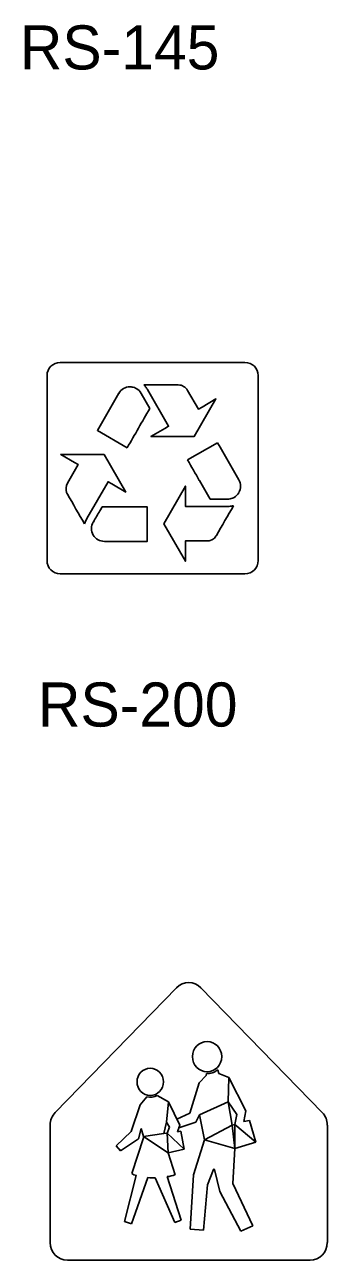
# Model space of a CAD drawing. Extents: x 42133 to 45533, y 41351 to 47951.
# Drawn here: x 43339.4 to 43390.9, y 42003.1 to 42213.3 of the extents above; entities that cross this region are included whole.
import ezdxf

# ---------------------------------------------------------------- set-up
doc = ezdxf.new("R2010")
doc.units = 0
doc.layers.add('P_TRAF_SIGN_SignDetails', color=7, linetype='Continuous')

msp = doc.modelspace()

# ---------------------------------------------------------------- linework, layer by layer
at = {"layer": 'P_TRAF_SIGN_SignDetails'}
for p, q in [((43376.91, 42155.87), (43345.43, 42155.87)), ((43343.18, 42153.62), (43343.18, 42122.14)), ((43379.16, 42122.14), (43379.16, 42153.62)), ((43345.43, 42119.88), (43376.91, 42119.88)), ((43365.24, 42049.48), (43344.58, 42028.24)), ((43369.41, 42049.48), (43390.07, 42028.24)), ((43372.19, 42035.5), (43372.3, 42035.42)), ((43372.3, 42035.42), (43372.47, 42034.89)), ((43367.52, 42028.11), (43369.1, 42033.31)), ((43369.1, 42033.31), (43370.32, 42034.52)), ((43370.34, 42034.89), (43370.32, 42034.52)), ((43370.32, 42034.52), (43370.34, 42034.89)), ((43372.47, 42034.89), (43374.15, 42034.22)), ((43374.02, 42030.08), (43374.15, 42034.22)), ((43374.15, 42034.22), (43377.03, 42028.55)), ((43361.96, 42031.14), (43363.86, 42030.06)), ((43361.96, 42031.14), (43363.86, 42030.06)), ((43357.52, 42025), (43359.03, 42029.53)), ((43357.52, 42025), (43359.03, 42029.53)), ((43359.03, 42029.53), (43360.21, 42030.89)), ((43359.03, 42029.53), (43360.21, 42030.89)), ((43363.53, 42026.61), (43363.86, 42030.06)), ((43365.79, 42026.1), (43363.86, 42030.06)), ((43365.79, 42026.1), (43363.86, 42030.06)), ((43363.86, 42030.06), (43365.79, 42026.1)), ((43363.86, 42030.06), (43365.79, 42026.1)), ((43363.95, 42029.87), (43363.95, 42029.87)), ((43364.16, 42029.46), (43364.16, 42029.46)), ((43364.36, 42029.04), (43364.36, 42029.04)), ((43374.02, 42030.08), (43369.14, 42027.87)), ((43369.14, 42027.87), (43374.02, 42030.08)), ((43375.54, 42027.88), (43374.02, 42030.08)), ((43374.73, 42026.1), (43374.02, 42030.08)), ((43374.02, 42030.08), (43375.54, 42027.88)), ((43375.54, 42027.88), (43374.02, 42030.08)), ((43374.02, 42030.08), (43374.73, 42026.1)), ((43375.54, 42027.88), (43374.02, 42030.08)), ((43374.02, 42030.08), (43374.73, 42026.1)), ((43364.56, 42028.63), (43364.56, 42028.63)), ((43364.76, 42028.21), (43364.76, 42028.21)), ((43364.97, 42027.8), (43364.97, 42027.8)), ((43365.16, 42027.39), (43365.16, 42027.39)), ((43365.3, 42027.11), (43367.52, 42028.11)), ((43369.14, 42027.87), (43368.52, 42026.58)), ((43370.03, 42023.59), (43369.14, 42027.87)), ((43375.18, 42026.2), (43375.54, 42027.88)), ((43375.18, 42026.2), (43375.54, 42027.88)), ((43377.03, 42028.55), (43376.72, 42026.69)), ((43376.72, 42026.69), (43377.7, 42026.89)), ((43377.7, 42026.89), (43378.77, 42023.17)), ((43343.71, 42026.1), (43343.71, 42006.13)), ((43354.95, 42022.56), (43357.52, 42025)), ((43354.95, 42022.56), (43357.52, 42025)), ((43359.24, 42025.5), (43358.77, 42023.76)), ((43359.24, 42025.5), (43358.77, 42023.76)), ((43359.61, 42024.13), (43359.24, 42025.5)), ((43359.61, 42024.13), (43359.24, 42025.5)), ((43363.53, 42026.61), (43363.07, 42024.69)), ((43364.03, 42025.77), (43363.53, 42026.61)), ((43363.63, 42024.73), (43364.03, 42025.77)), ((43365.79, 42026.1), (43365.4, 42024.95)), ((43365.4, 42024.95), (43365.79, 42026.1)), ((43365.79, 42026.1), (43365.4, 42024.95)), ((43365.79, 42026.1), (43365.4, 42024.95)), ((43365.4, 42024.95), (43366, 42025.06)), ((43365.4, 42024.95), (43366, 42025.06)), ((43368.52, 42026.58), (43365.62, 42025.61)), ((43365.66, 42025.73), (43365.66, 42025.73)), ((43365.66, 42025.73), (43365.66, 42025.73)), ((43366, 42025.06), (43366.57, 42022.01)), ((43366, 42025.06), (43366.57, 42022.01)), ((43374.73, 42026.1), (43370.03, 42023.59)), ((43375.18, 42026.2), (43374.73, 42026.1)), ((43374.73, 42026.1), (43375.15, 42022.11)), ((43375.15, 42022.11), (43375.18, 42026.2)), ((43375.15, 42022.11), (43375.18, 42026.2)), ((43378.77, 42023.17), (43375.18, 42026.2)), ((43375.18, 42026.2), (43378.77, 42023.17)), ((43390.94, 42026.1), (43390.94, 42006.13)), ((43358.77, 42023.76), (43355.7, 42021.73)), ((43358.77, 42023.76), (43355.7, 42021.73)), ((43357.6, 42017.86), (43359.59, 42023.91)), ((43357.6, 42017.86), (43359.59, 42023.91)), ((43359.59, 42023.91), (43359.61, 42024.13)), ((43359.59, 42023.91), (43359.61, 42024.13)), ((43363.07, 42024.69), (43359.61, 42024.13)), ((43363.07, 42024.69), (43359.61, 42024.13)), ((43359.61, 42024.13), (43363.84, 42021.36)), ((43359.61, 42024.13), (43363.84, 42021.36)), ((43363.63, 42024.73), (43363.07, 42024.69)), ((43366.57, 42022.01), (43363.63, 42024.73)), ((43363.84, 42021.36), (43363.63, 42024.73)), ((43363.63, 42024.73), (43366.57, 42022.01)), ((43368.14, 42017.66), (43370.03, 42023.59)), ((43375.15, 42022.11), (43370.03, 42023.59)), ((43370.03, 42023.59), (43375.15, 42022.11)), ((43370.03, 42023.59), (43375.15, 42022.11)), ((43375.15, 42022.11), (43370.03, 42023.59)), ((43375.15, 42022.11), (43370.03, 42023.59)), ((43370.03, 42023.59), (43375.15, 42022.11)), ((43370.03, 42023.59), (43375.15, 42022.11)), ((43375.15, 42022.11), (43370.03, 42023.59)), ((43375.15, 42022.11), (43370.03, 42023.59)), ((43370.03, 42023.59), (43375.15, 42022.11)), ((43378.77, 42023.17), (43375.15, 42022.11)), ((43355.7, 42021.73), (43354.95, 42022.56)), ((43355.7, 42021.73), (43354.95, 42022.56)), ((43355.63, 42021.82), (43355.83, 42021.82)), ((43366.57, 42022.01), (43363.84, 42021.36)), ((43366.57, 42022.01), (43363.84, 42021.36)), ((43363.84, 42021.36), (43365.01, 42017.66)), ((43363.84, 42021.36), (43365.01, 42017.66)), ((43375.15, 42022.11), (43374.85, 42016.14)), ((43371.52, 42018.53), (43370.52, 42015.93)), ((43372.6, 42014.77), (43371.72, 42018.53)), ((43356.38, 42009.69), (43358.39, 42017.54)), ((43356.38, 42009.69), (43358.39, 42017.54)), ((43360.37, 42017.18), (43357.55, 42009.32)), ((43360.37, 42017.18), (43357.55, 42009.32)), ((43364.97, 42009.51), (43361.61, 42017.12)), ((43364.97, 42009.51), (43361.61, 42017.12)), ((43363.65, 42017.33), (43366.04, 42009.93)), ((43363.65, 42017.33), (43366.04, 42009.93)), ((43367.56, 42008.38), (43368.14, 42017.66)), ((43370.52, 42015.93), (43369.83, 42008.21)), ((43376.21, 42008.02), (43372.6, 42014.77)), ((43374.85, 42016.14), (43378.22, 42008.97)), ((43357.55, 42009.32), (43356.38, 42009.69)), ((43357.55, 42009.32), (43356.38, 42009.69)), ((43366.04, 42009.93), (43364.97, 42009.51)), ((43366.04, 42009.93), (43364.97, 42009.51)), ((43369.83, 42008.21), (43367.56, 42008.38)), ((43378.22, 42008.97), (43376.21, 42008.02)), ((43346.66, 42003.09), (43387.99, 42003.09))]:
    msp.add_line(p, q, dxfattribs=at)
for points in [[(43365.54, 42152.04), (43359.67, 42152.04)], [(43365.54, 42152.04), (43359.67, 42152.04)], [(43365.54, 42152.04), (43359.67, 42152.04)], [(43360.28, 42151.24), (43363.89, 42145), (43363.26, 42144.63), (43360.89, 42143.27), (43368.27, 42143.27), (43371.96, 42149.65), (43369.59, 42148.28), (43368.96, 42147.92), (43367.13, 42151.11)], [(43360.28, 42151.24), (43363.89, 42145), (43363.26, 42144.63), (43360.89, 42143.27), (43368.27, 42143.27), (43371.96, 42149.65), (43369.59, 42148.28), (43368.96, 42147.92), (43367.13, 42151.11)], [(43360.28, 42151.24), (43363.89, 42145), (43363.26, 42144.63), (43360.89, 42143.27), (43368.27, 42143.27), (43371.96, 42149.65), (43369.59, 42148.28), (43368.96, 42147.92), (43367.13, 42151.11)], [(43355.41, 42150.61), (43351.76, 42144.29), (43356.85, 42141.36)], [(43355.41, 42150.61), (43351.76, 42144.29), (43356.85, 42141.36)], [(43355.41, 42150.61), (43351.76, 42144.29), (43356.85, 42141.36)], [(43360.69, 42148.02), (43359.2, 42150.6)], [(43360.69, 42148.02), (43359.2, 42150.6)], [(43360.69, 42148.02), (43359.2, 42150.6)], [(43372.21, 42142.21), (43367.13, 42139.28)], [(43372.21, 42142.21), (43367.13, 42139.28)], [(43372.21, 42142.21), (43367.13, 42139.28)], [(43349.97, 42129.31), (43353.59, 42135.56), (43354.21, 42135.2), (43356.58, 42133.82), (43352.89, 42140.21), (43345.51, 42140.22), (43347.88, 42138.86), (43348.51, 42138.49), (43346.66, 42135.3)], [(43349.97, 42129.31), (43353.59, 42135.56), (43354.21, 42135.2), (43356.58, 42133.82), (43352.89, 42140.21), (43345.51, 42140.22), (43347.88, 42138.86), (43348.51, 42138.49), (43346.66, 42135.3)], [(43349.97, 42129.31), (43353.59, 42135.56), (43354.21, 42135.2), (43356.58, 42133.82), (43352.89, 42140.21), (43345.51, 42140.22), (43347.88, 42138.86), (43348.51, 42138.49), (43346.66, 42135.3)], [(43373.98, 42131.35), (43366.76, 42131.36), (43366.76, 42132.08), (43366.76, 42134.82), (43363.07, 42128.43), (43366.75, 42122.04), (43366.75, 42124.77)], [(43373.98, 42131.35), (43366.76, 42131.36), (43366.76, 42132.08), (43366.76, 42134.82), (43363.07, 42128.43), (43366.75, 42122.04), (43366.75, 42124.77)], [(43373.98, 42131.35), (43366.76, 42131.36), (43366.76, 42132.08), (43366.76, 42134.82), (43363.07, 42128.43), (43366.75, 42122.04), (43366.75, 42124.77)], [(43370.97, 42132.61), (43373.95, 42132.61)], [(43370.97, 42132.61), (43373.95, 42132.61)], [(43370.97, 42132.61), (43373.95, 42132.61)], [(43352.96, 42125.41), (43360.25, 42125.41), (43360.25, 42131.28), (43352.57, 42131.28)], [(43352.96, 42125.41), (43360.25, 42125.41), (43360.25, 42131.28), (43352.57, 42131.28)], [(43352.96, 42125.41), (43360.25, 42125.41), (43360.25, 42131.28), (43352.57, 42131.28)], [(43366.75, 42124.77), (43366.75, 42125.5), (43370.43, 42125.49)], [(43366.75, 42124.77), (43366.75, 42125.5), (43370.43, 42125.49)], [(43366.75, 42124.77), (43366.75, 42125.5), (43370.43, 42125.49)], [(43365.62, 42025.61), (43365.79, 42026.1), (43365.3, 42027.11)], [(43370.03, 42023.59), (43374.73, 42026.1), (43375.15, 42022.11)]]:
    msp.add_lwpolyline(points, dxfattribs=at)
for centre, radius, start, end in [((43345.43, 42153.62), 2.25, 90, 180), ((43376.91, 42153.62), 2.25, 360, 90), ((43357.32, 42149.53), 2.18, 90.2881, 150.4934), ((43357.32, 42149.53), 2.18, 90.2881, 150.4934), ((43357.32, 42149.53), 2.18, 90.2881, 150.4934), ((43357.26, 42149.32), 2.39, 79.4497, 88.9151), ((43357.26, 42149.32), 2.39, 79.4497, 88.9151), ((43357.26, 42149.32), 2.39, 79.4497, 88.9151), ((43357.31, 42149.56), 2.15, 59.845, 79.6127), ((43357.31, 42149.56), 2.15, 59.845, 79.6127), ((43357.31, 42149.56), 2.15, 59.845, 79.6127), ((43357.33, 42149.55), 2.15, 29.1343, 60.3192), ((43357.33, 42149.55), 2.15, 29.1343, 60.3192), ((43357.33, 42149.55), 2.15, 29.1343, 60.3192), ((43355.02, 42147.7), 6.37, 40.2231, 43.031), ((43355.02, 42147.7), 6.37, 40.2231, 43.031), ((43355.02, 42147.7), 6.37, 40.2231, 43.031), ((43356.96, 42149.31), 3.84, 32.0576, 40.4922), ((43356.96, 42149.31), 3.84, 32.0576, 40.4922), ((43356.96, 42149.31), 3.84, 32.0576, 40.4922), ((43357.55, 42149.7), 3.14, 29.4949, 31.8189), ((43357.55, 42149.7), 3.14, 29.4949, 31.8189), ((43357.55, 42149.7), 3.14, 29.4949, 31.8189), ((43365.55, 42150.24), 1.8, 59.8496, 90.2116), ((43365.55, 42150.24), 1.8, 59.8496, 90.2116), ((43365.55, 42150.24), 1.8, 59.8496, 90.2116), ((43365.49, 42150.18), 1.88, 29.8933, 59.4501), ((43365.49, 42150.18), 1.88, 29.8933, 59.4501), ((43365.49, 42150.18), 1.88, 29.8933, 59.4501), ((47757.12, 39606.87), 5078, 149.972, 150.05872), ((47757.12, 39606.87), 5078, 149.972, 150.05872), ((47757.12, 39606.87), 5078, 149.972, 150.05872), ((37330.19, 38650.89), 6978.2, 29.96119, 30.021057), ((37330.19, 38650.89), 6978.2, 29.96119, 30.021057), ((37330.19, 38650.89), 6978.2, 29.96119, 30.021057), ((44966.95, 43058.07), 1844.89, 209.86918, 209.99371), ((44966.95, 43058.07), 1844.89, 209.86918, 209.99371), ((44966.95, 43058.07), 1844.89, 209.86918, 209.99371), ((43348.26, 42134.37), 1.85, 149.8417, 200.1132), ((43348.26, 42134.37), 1.85, 149.8417, 200.1132), ((43348.26, 42134.37), 1.85, 149.8417, 200.1132), ((49178.28, 45485.16), 6705.55, 209.966285, 209.997756), ((49178.28, 45485.16), 6705.55, 209.966285, 209.997756), ((49178.28, 45485.16), 6705.55, 209.966285, 209.997756), ((43373.97, 42134.79), 2.19, 330.3525, 30.4051), ((43373.97, 42134.79), 2.19, 330.3525, 30.4051), ((43373.97, 42134.79), 2.19, 330.3525, 30.4051), ((43348.13, 42134.34), 1.72, 200.5633, 210.612), ((43348.13, 42134.34), 1.72, 200.5633, 210.612), ((43348.13, 42134.34), 1.72, 200.5633, 210.612), ((46221.28, 43788.31), 3316.93, 209.92784, 210.02913), ((46221.28, 43788.31), 3316.93, 209.92784, 210.02913), ((46221.28, 43788.31), 3316.93, 209.92784, 210.02913), ((43373.96, 42134.86), 2.25, 269.8225, 291.2489), ((43373.96, 42134.86), 2.25, 269.8225, 291.2489), ((43373.96, 42134.86), 2.25, 269.8225, 291.2489), ((43374.02, 42134.69), 2.07, 291.4506, 300.4996), ((43374.02, 42134.69), 2.07, 291.4506, 300.4996), ((43374.02, 42134.69), 2.07, 291.4506, 300.4996), ((43373.98, 42134.79), 2.17, 299.9829, 330.0285), ((43373.98, 42134.79), 2.17, 299.9829, 330.0285), ((43373.98, 42134.79), 2.17, 299.9829, 330.0285), ((44150.54, 41667.88), 922.77, 149.90113, 150.04055), ((44150.54, 41667.88), 922.77, 149.90113, 150.04055), ((44150.54, 41667.88), 922.77, 149.90113, 150.04055), ((43463, 42066.48), 128.04, 149.5963, 149.9267), ((43463, 42066.48), 128.04, 149.5963, 149.9267), ((43463, 42066.48), 128.04, 149.5963, 149.9267), ((41027.85, 43482.69), 2708.26, 329.94734, 330.07138), ((41027.85, 43482.69), 2708.26, 329.94734, 330.07138), ((41027.85, 43482.69), 2708.26, 329.94734, 330.07138), ((43373.97, 42134.14), 2.79, 270.0063, 271.2927), ((43373.97, 42134.14), 2.79, 270.0063, 271.2927), ((43373.97, 42134.14), 2.79, 270.0063, 271.2927), ((43373.95, 42134.8), 3.45, 271.4704, 277.7116), ((43373.95, 42134.8), 3.45, 271.4704, 277.7116), ((43373.95, 42134.8), 3.45, 271.4704, 277.7116), ((43373.74, 42136.47), 5.12, 277.5274, 279.6232), ((43373.74, 42136.47), 5.12, 277.5274, 279.6232), ((43373.74, 42136.47), 5.12, 277.5274, 279.6232), ((43373.39, 42138.49), 7.18, 279.6553, 281.1426), ((43373.39, 42138.49), 7.18, 279.6553, 281.1426), ((43373.39, 42138.49), 7.18, 279.6553, 281.1426), ((43372.47, 42143.15), 11.93, 281.1753, 282.0613), ((43372.47, 42143.15), 11.93, 281.1753, 282.0613), ((43372.47, 42143.15), 11.93, 281.1753, 282.0613), ((43355.69, 42126.48), 6.4, 159.8846, 162.6887), ((43355.69, 42126.48), 6.4, 159.8846, 162.6887), ((43355.69, 42126.48), 6.4, 159.8846, 162.6887), ((43354.18, 42127.03), 4.79, 156.1003, 159.851), ((43354.18, 42127.03), 4.79, 156.1003, 159.851), ((43354.18, 42127.03), 4.79, 156.1003, 159.851), ((43353.29, 42127.43), 3.82, 150.4088, 156.0915), ((43353.29, 42127.43), 3.82, 150.4088, 156.0915), ((43353.29, 42127.43), 3.82, 150.4088, 156.0915), ((43352.93, 42127.59), 2.17, 149.2567, 210.3629), ((43352.93, 42127.59), 2.17, 149.2567, 210.3629), ((43352.93, 42127.59), 2.17, 149.2567, 210.3629), ((43352.94, 42127.58), 2.16, 209.9186, 270.5534), ((43352.94, 42127.58), 2.16, 209.9186, 270.5534), ((43352.94, 42127.58), 2.16, 209.9186, 270.5534), ((43370.5, 42127.22), 1.71, 291.2759, 300.2679), ((43370.5, 42127.22), 1.71, 291.2759, 300.2679), ((43370.5, 42127.22), 1.71, 291.2759, 300.2679), ((43370.46, 42127.32), 1.82, 299.9041, 325.2107), ((43370.46, 42127.32), 1.82, 299.9041, 325.2107), ((43370.46, 42127.32), 1.82, 299.9041, 325.2107), ((43370.55, 42127.24), 1.69, 325.4846, 330.584), ((43370.55, 42127.24), 1.69, 325.4846, 330.584), ((43370.55, 42127.24), 1.69, 325.4846, 330.584), ((43370.43, 42127.41), 1.91, 269.8464, 291.0666), ((43370.43, 42127.41), 1.91, 269.8464, 291.0666), ((43370.43, 42127.41), 1.91, 269.8464, 291.0666), ((43345.43, 42122.14), 2.25, 180, 270), ((43376.91, 42122.14), 2.25, 270, 0)]:
    msp.add_arc(centre, radius, start, end, dxfattribs=at)
for centre, major_axis, start_param, end_param in [((43367.32, 42047.33), (0, 3.03), 5.49782, 7.068583), ((43370.63, 42037.26), (0, -2.39), 6.157517, 7.020334), ((43360.72, 42033.7), (0, -2.86), 6.095326, 6.744556), ((43360.72, 42033.7), (0, -2.86), 6.095326, 6.744556), ((43346.66, 42026.1), (0, -3.03), 3.926991, 4.712389), ((43387.99, 42026.1), (0, 3.03), 4.712389, 5.49775), ((43371.62, 42018.5), (0, 0.108), 5.046905, 7.52285), ((43358.7, 42019.58), (0, -2.06), 5.703441, 6.132872), ((43358.7, 42019.58), (0, -2.06), 5.703441, 6.132872), ((43361.17, 42021.17), (0, -4.07), 6.078852, 6.394937), ((43361.17, 42021.17), (0, -4.07), 6.078852, 6.394937), ((43363.28, 42021.94), (0, -4.63), 0.083253, 0.393979), ((43363.28, 42021.94), (0, -4.63), 0.083253, 0.393979), ((43346.66, 42006.13), (0, -3.03), 4.712389, 6.283185), ((43387.99, 42006.13), (0, 3.03), 3.141593, 4.712389)]:
    msp.add_ellipse(centre, major_axis=major_axis, ratio=0.9732, start_param=start_param, end_param=end_param, dxfattribs=at)
for centre, major_axis in [((43370.45, 42037.74), (0, 2.57)), ((43360.76, 42033.45), (0, 2.31))]:
    msp.add_ellipse(centre, major_axis=major_axis, ratio=0.9732, dxfattribs=at)

# ---------------------------------------------------------------- texts
for s, p in [('RS-145', (43338.55, 42205.72)), ('RS-200', (43341.63, 42093.91))]:
    msp.add_text(s, height=7.5, dxfattribs=at).set_placement(p)

doc.saveas('drawing.dxf')
